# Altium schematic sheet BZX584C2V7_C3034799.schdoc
size 127 x 101 mm
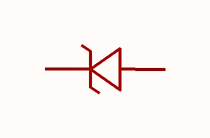
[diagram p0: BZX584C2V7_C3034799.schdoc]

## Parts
D?  bzx584c2v7_c3034799  [SOD-523F_L1.2-W0.8-LS1.7-RD]  (value not drawn)

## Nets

Not connected (* = marked no-connect by the designer): D? 1(K) 2(A)

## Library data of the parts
D? = bzx584c2v7_c3034799: 二极管配置:1个独立式;稳压值(标称值):2.7V;稳压值(范围值):2.5V~2.9V;耗散功率(Pd):150mW;; Manufacturer: CJ(江苏长电/长晶); AddInBom: yes; ModelId: 1a3524270898456e95fda80dc56db1b2; ModelName: SOD-523F_L1.2-W0.8-H0.6-LS1.6; ModelTransform: 62.992,31.496,0,0,0,0,-0.005,0.16,0; Diode Configuration: 1个独立式; Zener Voltage(Nom): 2.7V; Reverse Leakage Current (Ir): 20uA@1V; Pd - Power Dissipation: 150mW; Impedance(Zzt): 100Ω; Impedance(Zzk): 600Ω; Operating Junction Temperature Range: -55℃~+150℃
